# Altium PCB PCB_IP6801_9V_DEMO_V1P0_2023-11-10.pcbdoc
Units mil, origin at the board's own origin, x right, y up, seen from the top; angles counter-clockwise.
Board outline 3645 x 2770 mil, 2 copper layers (Top Layer, Bottom Layer); 39 components, 30 nets, 121 pads, 103 vias.
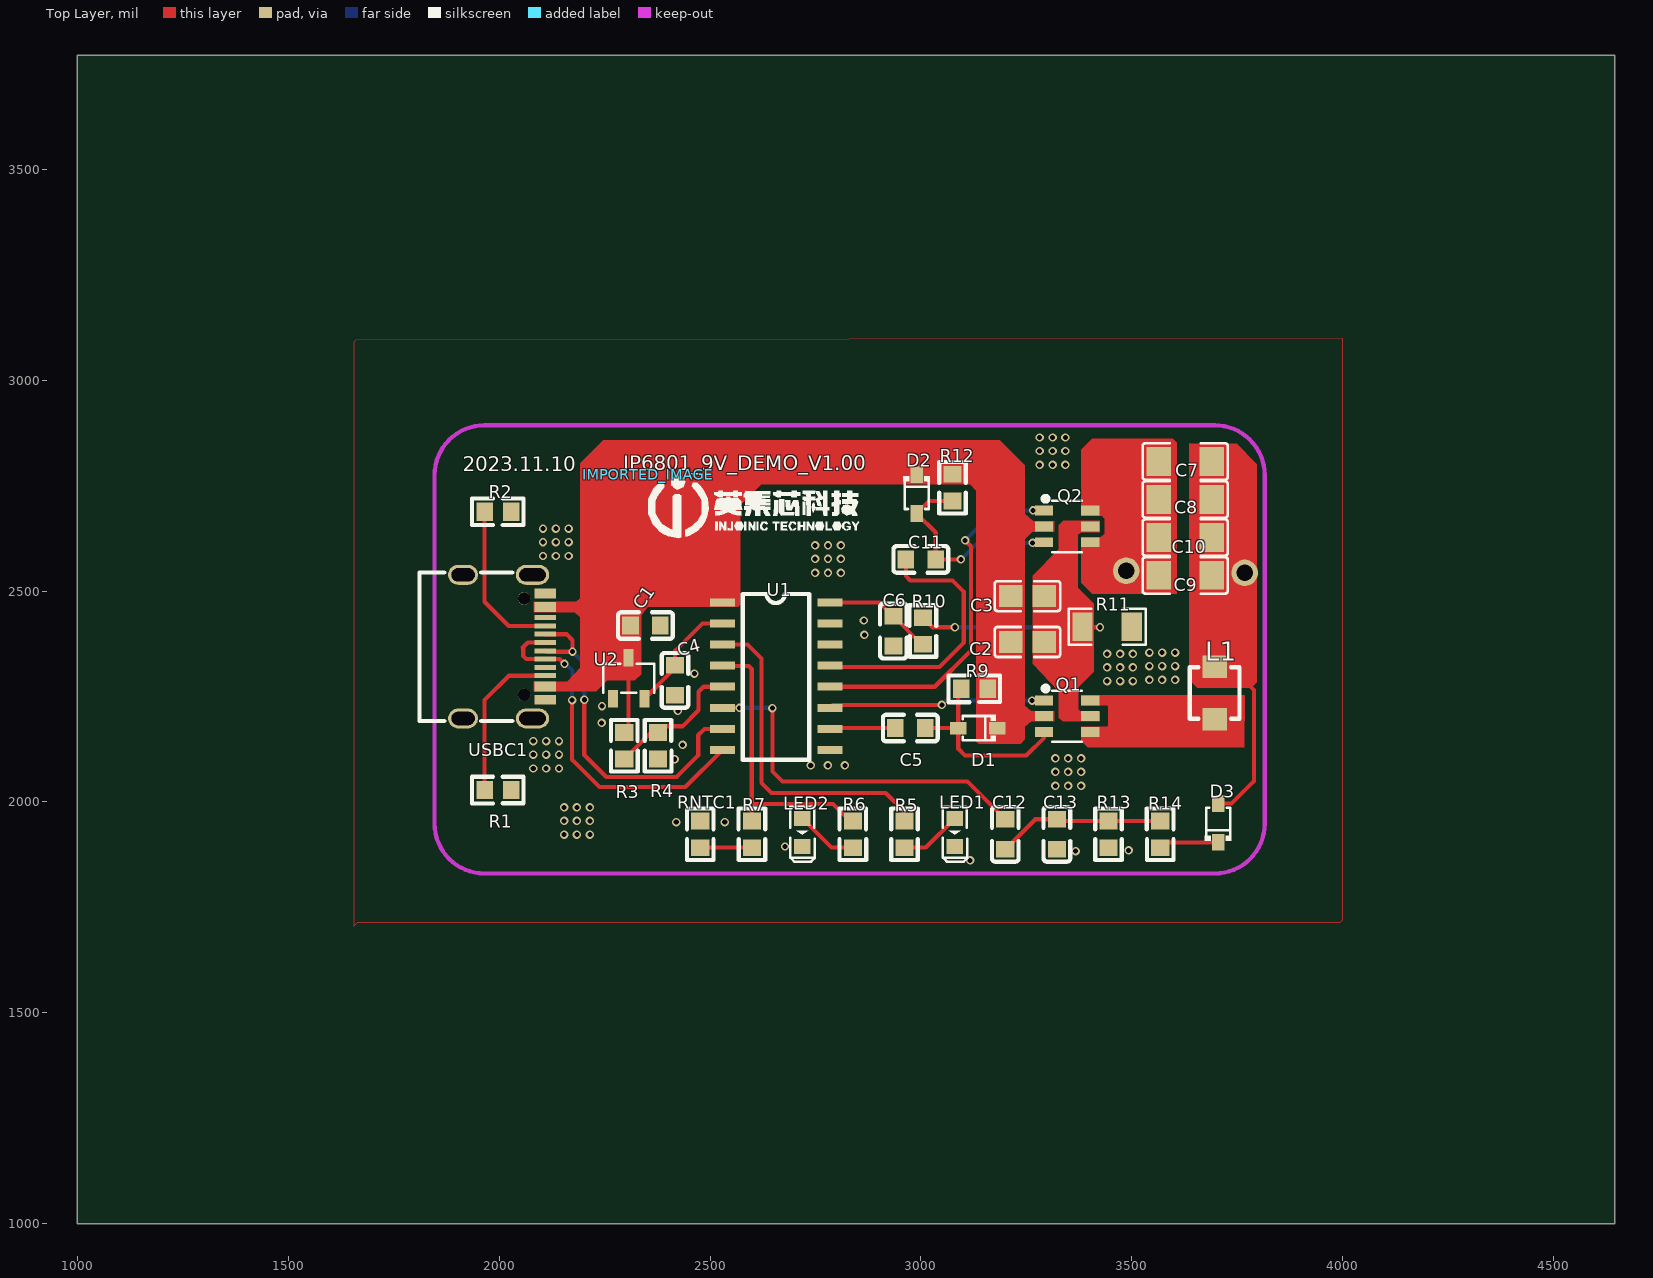
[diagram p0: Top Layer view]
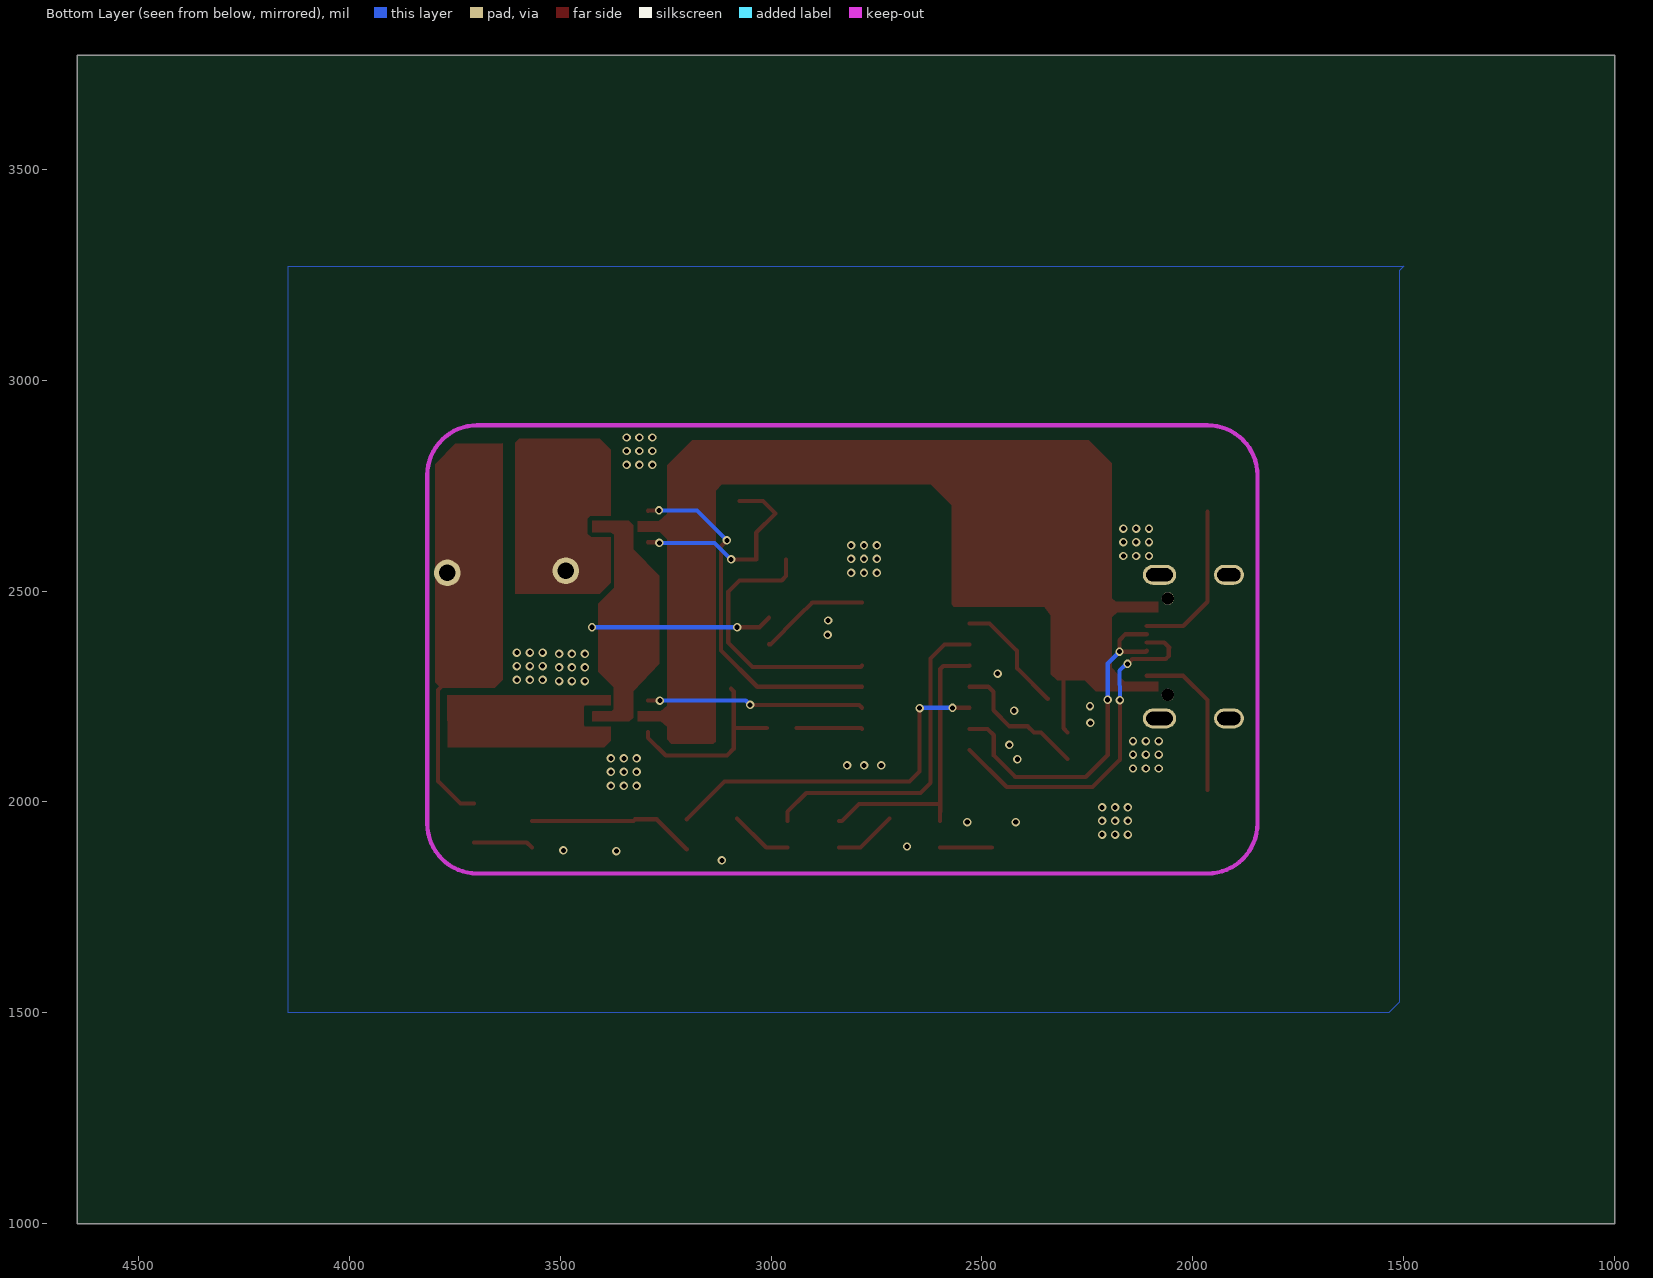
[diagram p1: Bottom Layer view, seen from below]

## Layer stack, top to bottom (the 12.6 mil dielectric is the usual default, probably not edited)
Top Layer: signal copper (thickness not stored)
Dielectric: dielectric 12.6, FR-4, Dk 4.8
Bottom Layer: signal copper (thickness not stored)

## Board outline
4645,1000 1000,1000 1000,3770 4645,3770

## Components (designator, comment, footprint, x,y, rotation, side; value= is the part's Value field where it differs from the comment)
C1 "4.7uF" C0603 2346.89,2418.11 r0 top
C2 "22uF" C0805 3252.89,2379.11 r180 top
C3 "22uF" C0805 3252.89,2488.11 r180 top
C4 "4.7uF" C0603 2416.89,2288.11 r90 top
C5 "100nF" C0603 2975,2175 r0 top
C6 "10nF" C0603 2934.93,2405.1 r90 top
C7 "100nF" C1206 3626.9,2807.1 r180 top
C8 "100nF" C1206 3626.9,2717.1 r180 top
C9 "100nF" C1206 3626.9,2537.1 r180 top
C10 "100nF" C1206 3626.9,2627.1 r180 top
C11 "100nF" C0603 3000,2575 r0 top
C12 "10nF" C0603 3200.34,1923.1 r270 top
C13 "10nF" C0603 3322.64,1923.1 r90 top
D1 "1N4148WS" SOD-323_L1.8-W1.3-LS2.5-RD 3135,2175 r180 top
D2 "1N4148WS" SOD-323_L1.8-W1.3-LS2.5-RD 2990,2730 r270 top
D3 "1N4148WS" SOD-323_L1.8-W1.3-LS2.5-RD 3705,1950 r90 top
IMPORTED_IMAGE "IMPORTED_IMAGE" IMPORTED_IMAGE 2353.85,2775.15 r0 top
L1 "6.3uH" IND-SMD_L4.5-W3.0 3696.89,2258.11 r90 top
LED1 "LED" LED0603_GREEN 3080.85,1927.24 r270 top
LED2 "LED" LED0603_RED 2719.11,1927.24 r270 top
Q1 "AP10G02LI" SOT-23-6_L2.9-W1.6-P0.95-LS2.7-BL 3346.9,2203.1 r270 top
Q2 "AP10G02LI" SOT-23-6_L2.9-W1.6-P0.95-LS2.7-BL 3346.9,2653.1 r270 top
R1 "5.1k" R0603 1996.89,2028.11 r180 top
R2 "5.1k" R0603 1996.89,2688.11 r180 top
R3 "33k" R0603 2296.89,2133.11 r90 top
R4 "11k" R0603 2376.89,2133.11 r90 top
R5 "1k" R0603 2961.32,1923.1 r90 top
R6 "1k" R0603 2838.84,1923.1 r90 top
R7 "3.3k" R0603 2599.38,1923.12 r270 top
R9 "1k" R0603 3126.89,2268.11 r180 top
R10 "3.3k" R0603 3004.89,2405.11 r270 top
R11 "20mR" R1206 3441.89,2415.11 r0 top
R12 "1k" R0603 3075,2745 r270 top
R13 "33k" R0603 3445.15,1923.1 r90 top
R14 "3.3k" R0603 3567.43,1923.12 r270 top
RNTC1 "10k" R0603 2476.89,1923.12 r270 top
U1 "IP6801" SOP16L 2656.9,2298.09 r0 top
U2 "LR8321A-T50" SOT-23-3_L2.9-W1.6-P1.90-LS2.8-BR 2306.89,2293.11 r270 top
USBC1 "TYPE-C-31-M-12" USB-C_SMD-TYPE-C-31-M-12 2011.89,2368.11 r270 top

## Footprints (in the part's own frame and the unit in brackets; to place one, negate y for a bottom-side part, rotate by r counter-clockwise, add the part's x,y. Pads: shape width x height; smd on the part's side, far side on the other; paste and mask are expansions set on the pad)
C0603 [mm]
  rect 1x1.1 smd paste+0 mask+0.102: 1(-0.9,0) 2(0.9,0)
  silkscreen extent -1.65,-0.8 1.65,0.8
C0805 [mm]
  rect 1.41x1.35 smd paste-100 mask+0.051: 1(-1,0) 2(1,0)
  silkscreen extent -1.96,-0.9 1.96,0.9
C1206 [mm]
  rect 1.485x1.728 smd paste-100 mask+0.051: 1(-1.593,0) 2(1.593,0)
  silkscreen extent -2.56,-1.09 2.56,1.09
IMPORTED_IMAGE [mil]
  silkscreen extent 0,-150 500,0
IND-SMD_L4.5-W3.0 [mm]
  rect 1.35x1.5 smd paste+0 mask+0.05: 1(-1.575,0) 2(1.575,0)
  silkscreen extent -1.55,-1.5 1.55,1.5
LED0603_GREEN [mm]
  rect 0.9x1 smd paste+0 mask+0.051: 1(-0.85,0) 2(0.85,0)
  silkscreen extent -1.54,-0.73 1.75,0.73
LED0603_RED [mm]
  rect 0.9x1 smd paste+0 mask+0.051: 1(-0.85,0) 2(0.85,0)
  silkscreen extent -1.54,-0.73 1.75,0.73
R0603 [mm]
  rect 1x1.1 smd paste+0 mask+0.102: 1(-0.8,0) 2(0.8,0)
  silkscreen extent -1.55,-0.8 1.55,0.81
R1206 [mil]
  rect 47.54x66.97 smd paste-3937.01 mask+2: 1(-58.22,0) 2(58.22,0)
  silkscreen extent -91,-42 91,42
SOD-323_L1.8-W1.3-LS2.5-RD [mm]
  rect 1x0.75 smd paste+0 mask+0.051: 1(-1.173,0) 2(1.173,0)
  silkscreen extent -1.08,-0.8 0.9,0.8
SOP16L [mm]
  rect 1.52x0.48 smd paste+0 mask+0.051: 1(-3.238,4.445) 2(-3.238,3.175) 3(-3.238,1.905) 4(-3.239,0.635) 5(-3.239,-0.635) 6(-3.239,-1.905) 7(-3.239,-3.175) 8(-3.239,-4.445) 9(3.238,-4.445) 10(3.238,-3.175) 11(3.238,-1.905) 12(3.238,-0.635) 13(3.238,0.635) 14(3.238,1.905) 15(3.238,3.175) 16(3.239,4.445)
  silkscreen extent -2.02,-5.05 1.99,4.95
SOT-23-3_L2.9-W1.6-P1.90-LS2.8-BR [mm]
  rect 1.07x0.6 smd paste+0 mask+0.051: 1(1.235,-0.95) 2(1.235,0.95) 3(-1.235,0)
  silkscreen extent -0.88,-1.54 0.88,1.54
SOT-23-6_L2.9-W1.6-P0.95-LS2.7-BL [mm]
  rect 0.6x1.1 smd paste+0 mask+0.051: 1(-0.95,-1.4) 2(0,-1.4) 3(0.95,-1.4) 4(0.95,1.4) 5(0,1.4) 6(-0.95,1.4)
  silkscreen extent -1.82,-1.45 1.54,0.89
USB-C_SMD-TYPE-C-31-M-12 [mm]
  oval 1.2x2 hole 0.8 slot 1.6 at 90 deg paste+0 mask+0.051: 0(-4.325,1.706) 1(4.325,1.706)
  oval 1.2x1.8 hole 0.8 slot 1.4 at 90 deg paste+0 mask+0.051: 2(4.325,-2.474) 3(-4.325,-2.474)
  rect 0.3x1.3 smd paste-100 mask+0.051: A1(-3.35,2.474) A4(-2.55,2.474) A5(-1.25,2.474) A6(-0.25,2.474) A7(0.25,2.474) A8(1.25,2.474) A9(2.55,2.474) A12(3.35,2.474) B1(3.05,2.474) B4(2.25,2.474) B5(1.75,2.474) B6(0.75,2.474) B7(-0.75,2.474) B8(-1.75,2.474) B9(-2.25,2.474) B12(-3.05,2.474)
  round 0.75 hole 0.75 unplated paste+0: ""(-2.9,1.206) ""(2.9,1.206)
  silkscreen extent -4.47,-5.09 4.47,0.49

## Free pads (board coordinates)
  round 62.99 hole 39.37 paste+0 mask+2: 1(3486.89,2548.11) 2(3767.89,2543.11)

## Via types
v1: diameter 20, hole 12, Top Layer to Bottom Layer, tented both sides, 103 vias

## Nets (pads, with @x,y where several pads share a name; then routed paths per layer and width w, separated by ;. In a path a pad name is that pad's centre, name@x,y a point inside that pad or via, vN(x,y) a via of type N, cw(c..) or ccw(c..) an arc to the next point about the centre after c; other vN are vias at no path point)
C5_2: C5.2 D1.2 Q1.3 R9.2 | length 463.9
  Top Layer w10: C5.2 D1.2 3088.84,2261.55 R9.2 ; D1.2 3088.8,2126.2 3105,2110 3250,2110 3291.8,2151.8 Q1.3
C9_2: C7.2 C8.2 C9.2 C10.2 pad.1 Q2.4 Q2.6
C11_2: C11.2 D2.2 Q2.3 R12.2 | length 498.1
  Top Layer w10: R12.2 3019.66,2713.5 D2.2 3035.43,2638.4 C11.2 v1(3095,2575) ; v1(3264.89,2614.11) 3266.49,2615.71 Q2.3
  Bottom Layer w10: v1(3095,2575) 3134.11,2614.11 v1(3264.89,2614.11)
C13_2: C12.2 C13.2 R13.2 R14.1 | length 398
  Top Layer w10: C12.2@3200.38,1887.67 3271.26,1958.55 3322.66,1958.55 3326.62,1954.59 R13.2 ; R13.2@3445.19,1954.61 R14.1
CC1: R1.2 USBC1.B5 | length 381.3
  Top Layer w10: R1.2 1965.39,2241.61 2022.99,2299.21 USBC1.B5
CC2: R2.2 USBC1.A5 | length 381.1
  Top Layer w10: R2.2 1965.39,2474.61 2022.68,2417.32 USBC1.A5
DM: U1.7 USBC1.A7 USBC1.B7 | length 844.1
  Top Layer w10: USBC1.A7 2111.46,2356.11 v1(2173.89,2356.11) 2173.89,2383.11 2159.36,2397.64 USBC1.B7 ; v1(2201.89,2242.11) 2201.89,2111.11 2253.89,2059.11 2420.89,2059.11 2471.89,2110.11 2471.89,2158.11 2486.91,2173.12 U1.7
  Bottom Layer w10: v1(2173.89,2356.11) 2201.89,2328.11 v1(2201.89,2242.11)
DP: U1.8 USBC1.A6 USBC1.B6 | length 841.1
  Top Layer w10: USBC1.A6 2067.73,2377.95 2055.89,2366.11 2056.89,2365.11 2056.89,2346.11 2064.42,2338.58 USBC1.B6 2143.42,2338.58 v1(2154.89,2327.11) ; v1(2172.89,2241.11) 2172.89,2100.11 2237.89,2035.11 2441.36,2035.11 U1.8
  Bottom Layer w10: v1(2154.89,2327.11) 2157.89,2327.11 2173.89,2311.11 v1(2172.89,2241.11)
DRV1H: C5.1 U1.10 | length 156
  Top Layer w10: U1.10 2786.3,2175 C5.1
DRV1L: Q1.1 U1.11 | length 514.6
  Top Layer w10: U1.11 2791.27,2230 v1(3050,2230) ; v1(3263.89,2240.11) 3291.39,2240.11 Q1.1
  Bottom Layer w10: v1(3050,2230) 3060.11,2240.11 v1(3263.89,2240.11)
DRV2H: C11.1 U1.13 | length 655.1
  Top Layer w10: U1.13 2787.4,2320.1 3043.9,2320.1 3101.9,2378.1 3101.9,2498.1 3075,2525 2975,2525 2964.6,2535.4 C11.1
DRV2L: Q2.1 U1.12 | length 853
  Top Layer w10: U1.12 3032.89,2273.11 3118.89,2359.11 3118.89,2606.11 v1(3105,2620) ; v1(3265.89,2691.11) Q2.1
  Bottom Layer w10: v1(3105,2620) 3176.11,2691.11 v1(3265.89,2691.11)
GND: C1.2 C4.1 C6.1 C13.1 LED1.2 LED2.2 R1.1 R2.1 R4.1 R11.2 R13.1 RNTC1.1 U1.9 U1.15 U2.1 USBC1.0 USBC1.A1 USBC1.A12 USBC1.B1 USBC1.B12
  other v1: 3116.89,1861.11 3366.89,1883.11 3492.89,1885.11 2677.89,1894.11 2153.89,1922.11 2184.39,1922.11 2214.89,1922.11 2419.89,1952.11 2534.89,1952.11 2153.89,1955.11 2184.39,1955.11 2214.89,1955.11 2153.89,1987.11 2184.39,1987.11 2214.89,1987.11 3318.89,2038.11 3349.39,2038.11 3379.89,2038.11 3318.89,2071.11 3349.39,2071.11 3379.89,2071.11 2080.89,2079.11 2111.39,2079.11 2141.89,2079.11 2738.89,2086.61 2779.39,2086.61 2819.89,2086.61 2415.89,2101.11 3318.89,2103.11 3349.39,2103.11 3379.89,2103.11 2080.89,2112.11 2111.39,2112.11 2141.89,2112.11 2434.89,2135.11 2080.89,2144.11 2111.39,2144.11 2141.89,2144.11 2242.89,2187.11 2423.89,2216.11 2243.89,2227.11 3441.89,2286.11 3472.39,2286.11 3502.89,2286.11 3541.89,2289.11 3572.39,2289.11 3602.89,2289.11 2462.89,2304.11 3441.89,2319.11 3472.39,2319.11 3502.89,2319.11 3541.89,2322.11 3572.39,2322.11 3602.89,2322.11 3441.89,2351.11 3472.39,2351.11 3502.89,2351.11 3541.89,2354.11 3572.39,2354.11 3602.89,2354.11 2865.89,2396.11 2864.89,2430.11 2749.39,2543.11 2779.89,2543.11 2810.39,2543.11 2749.39,2576.11 2779.89,2576.11 2810.39,2576.11 2103.89,2583.11 2134.39,2583.11 2164.89,2583.11 2749.39,2608.11 2779.89,2608.11 2810.39,2608.11 2103.89,2616.11 2134.39,2616.11 2164.89,2616.11 2103.89,2648.11 2134.39,2648.11 2164.89,2648.11 3281.89,2799.11 3312.39,2799.11 3342.89,2799.11 3281.89,2832.11 3312.39,2832.11 3342.89,2832.11 3281.89,2864.11 3312.39,2864.11 3342.89,2864.11
ISNS: C6.2 R10.2 U1.16 | length 261.7
  Top Layer w10: U1.16 2902.33,2473.11 C6.2 3001.83,2373.61 R10.2
L1_1: L1.1 Q1.4 Q1.6
LED1: R5.2 U1.3 | length 791
  Top Layer w10: U1.3 2588.89,2373.11 2621.89,2340.11 2621.89,2045.11 2645.89,2021.11 2916.89,2021.11 2961.29,1976.71 R5.2
LED1_1: LED1.1 R5.1 | length 148.2
  Top Layer w10: R5.1 3011.74,1891.6 LED1.1
LED2: R6.2 R7.1 U1.4 | length 694.3
  Top Layer w10: U1.4 2530.4,2322.11 2591.89,2322.11 2598.94,2315.06 2598.94,1990.89 ; R7.1 2598.89,1995.11 2791.89,1995.11 2832.39,1954.61 R6.2
LED2_1: LED2.1 R6.1 | length 148.4
  Top Layer w10: LED2.1 2788.22,1891.6 R6.1
PGND: C2.1 C3.1 Q1.5 Q2.5 R10.1 R11.1 | length 470.9
  Top Layer w10: R10.1 3027.38,2414.11 v1(3080.89,2414.11) ; R11.1 3384.67,2414.11 v1(3424.89,2414.11)
  Bottom Layer w10: v1(3080.89,2414.11) v1(3424.89,2414.11)
R14_2: D3.1 R14.2 | length 142.6
  Top Layer w10: R14.2 3579.64,1903.84 D3.1
RNTC1_2: R7.2 RNTC1.2 | length 122.5
  Top Layer w10: RNTC1.2 R7.2
U1_14: U1.14
USBC1_A8: USBC1.A8
USBC1_B8: USBC1.B8
VBUS: C1.1 C2.2 C3.2 D1.1 D2.1 Q1.2 Q2.2 R3.2 R9.1 R12.1 U1.1 U2.3 USBC1.A4 USBC1.A9 USBC1.B4 USBC1.B9 | length 181.3
  Top Layer w10: R3.2 2306.89,2174.61 U2.3
VC: C7.1 C8.1 C9.1 C10.1 D3.2 L1.2 pad.2 | length 438.6
  Top Layer w10: L1.2 3734.89,2320.11 3789.89,2265.11 3789.89,2049.11 3736.94,1996.16 D3.2
VCC: C4.2 U1.2 U2.2 | length 283.1
  Top Layer w10: U2.2 2416.89,2317.09 C4.2 2416.89,2358.11 2481.89,2423.11 U1.2
VDEM: C12.1 U1.6 | length 868.5
  Top Layer w10: U1.6 v1(2569.89,2223.11) ; v1(2647.89,2222.11) 2647.89,2072.11 2671.89,2048.11 3110.79,2048.11 C12.1@3200.39,1958.51
  Bottom Layer w10: v1(2569.89,2223.11) 2646.89,2223.11 v1(2647.89,2222.11)
VSNS: R3.1 R4.2 U1.5 | length 329.3
  Top Layer w10: R3.1 2359.88,2164.61 R4.2 2391.39,2179.11 2434.89,2179.11 2472.89,2217.11 2472.89,2261.11 2484.91,2273.12 U1.5
pads on no net: USBC1. USBC1.1 USBC1.2 USBC1.3

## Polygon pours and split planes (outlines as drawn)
GND on Bottom Layer (solid): 1500,3270 1510,3260 1510,1525 1535,1500 4145,1500 4145,3270
GND on Top Layer (solid): 1660,3095 1655,3090 1655,1705 1665,1715 3995,1715 4000,1720 4000,3100

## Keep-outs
Keep-Out Layer:
  lines w10: 1846.89,1948.23 ccw(c1965,1948.23) 1965,1830.12 ; 1846.89,2775 cw(c1965,2775) 1965,2893.11 ; 3697.28,1830.12 ccw(c3697.28,1948.23) 3815.39,1948.23 ; 3697.28,2893.11 cw(c3697.28,2775) 3815.39,2775

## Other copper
Top Layer:
  region net PGND: 3423.89,2666.11 3337.89,2666.11 3326.89,2656.11 3326.89,2599.11 3264.89,2536.11 3264.89,2328.11 3326.89,2262.11 3326.89,2199.11 3336.89,2191.11 3423.89,2191.11 3423.89,2214.11 3422.89,2215.11 3377.89,2215.11 3372.89,2220.11 3372.89,2272.11 3409.89,2309.11 3409.89,2470.11 3371.89,2508.11 3371.89,2633.11 3379.89,2639.11 3423.89,2639.11
  region net L1_1: 3379.89,2253.11 3379.89,2229.11 3441.89,2229.11 3444.89,2226.11 3444.89,2181.11 3441.89,2178.11 3379.89,2178.11 3379.89,2145.11 3395.89,2129.11 3766.89,2129.11 3767.89,2253.11
  region net VC: 3636.89,2850.11 3636.89,2289.11 3654.89,2271.11 3783.89,2271.11 3796.89,2284.11 3796.89,2801.11 3795.89,2802.11 3748.89,2849.11
  region net C9_2: 3606.89,2493.11 3606.89,2851.11 3596.89,2861.11 3406.89,2861.11 3380.89,2835.11 3380.89,2679.11 3379.89,2678.11 3428.89,2678.11 3435.89,2671.11 3435.89,2636.11 3426.89,2627.11 3379.89,2627.11 3379.89,2520.11 3406.89,2493.11
  region net VBUS: 2081.89,2262.11 2229.89,2262.11 2256.89,2288.11 2321.89,2288.11 2336.89,2303.11 2336.89,2443.11 2351.89,2463.11 2566.89,2463.11 2571.89,2468.11 2571.89,2703.11 2621.89,2753.11 3116.89,2753.11 3131.89,2738.11 3131.89,2143.11 3136.89,2138.11 3236.89,2138.11 3246.89,2148.11 3246.89,2178.11 3261.89,2191.11 3316.89,2191.11 3316.89,2215.11 3261.89,2215.11 3246.89,2228.11 3246.89,2623.11 3263.89,2640.11 3316.89,2640.11 3316.89,2665.11 3266.89,2665.11 3246.89,2683.11 3246.89,2798.11 3186.89,2858.11 2246.89,2858.11 2191.89,2803.11 2191.89,2483.11 2182.89,2474.11 2081.89,2474.11 2081.89,2450.11 2178.89,2450.11 2191.89,2438.11 2191.89,2318.11 2160.89,2285.11 2081.89,2285.11

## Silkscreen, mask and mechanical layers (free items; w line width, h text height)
Top Overlay:
  text "IP6801_9V_DEMO_V1.00" at 2293.89,2786.61 h35
  text "2023.11.10" at 1913.89,2783.61 h35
